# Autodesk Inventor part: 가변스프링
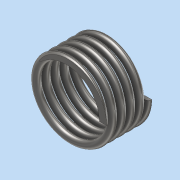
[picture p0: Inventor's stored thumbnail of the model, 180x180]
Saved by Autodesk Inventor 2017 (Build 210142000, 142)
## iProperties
Part Number: 가변스프링
Material: 스테인레스 스틸
Document SubType Name: Modeling
Designer: mrc
Density: 8 g/cm^3
Appearance: 반연마
Mass: 7.76831 g
Surface Area: 19.7146 cm^2
Volume: 0.971039 cm^3
Author: mrc
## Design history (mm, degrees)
sketch "스케치1"
  geometry: L1 (0, 0)-(10, 0); L2 (10, 0)-(10, 12.7); L3 (10, 12.7)-(0, 12.7); L4 (0, 12.7)-(0, 0); C1 r 1 at (10, 0)
  constraints: 8 end point, 2 parallel, 1 centre point, 1 coincident, 1 horizontal, 1 perpendicular
  dimensions: "d0" = 12.7 distance of L1.end L2.end (derived); "d1" = 20 diameter of L2 L4; "d2" = 2 diameter of C1
feature "코일1" sketch "스케치1" pitch "d3" = 10; turns "d5" = 5; dims "d4" = 12.7 (= d0), "d6" = 0, angle "d7" = 90 deg, angle "d8" = 90 deg, "d9" = 0, "d10" = 0
sketch "스케치2"
  geometry: L1 (-18.58, 0)-(18.58, 0); L2 (18.58, 0)-(18.58, 12.7); L3 (18.58, 12.7)-(-18.58, 12.7); L4 (-18.58, 12.7)-(-18.58, 0); 2 further points
  constraints: 8 end point, 2 parallel, 1 coincident, 1 horizontal, 1 midpoint, 1 perpendicular
  dimensions: "d11" = 12.7 distance of L1.end L2.end (= d0); "d12" = 37.15926 distance of L2.end L3.end
extrude "돌출1" sketch "스케치2" stored distance "d13" = 0; taper "d14" = 0 deg
node "솔리드1"
